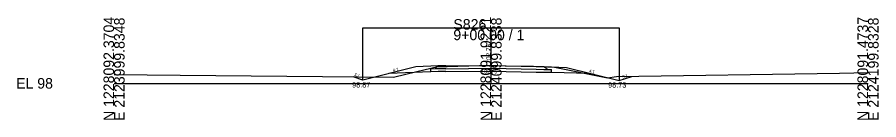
# Model space of a CAD drawing. Extents: x 2118382 to 2118616, y 1213030 to 1222057.
# Drawn here: x 2118381.9 to 2118610.4, y 1219530.1 to 1219557.4 of the extents above; entities that cross this region are included whole.
import ezdxf

# ---------------------------------------------------------------- set-up
doc = ezdxf.new("R2010")
doc.units = 0
for name, color, linetype in [('XS_CELL', 7, 'Continuous'), ('XS_M_DITCH', 7, 'Continuous'), ('XS_P_FINISHED_GRADE', 7, 'Continuous'), ('XS_P_FINISHED_GRADE_ELEV_TX', 7, 'Continuous'), ('XS_P_SUBGRADE_GRANULAR', 7, 'Continuous'), ('XS_P_SUBGRADE_PAVEMENT', 7, 'Continuous'), ('XS_P_TX_DCH', 7, 'Continuous'), ('XS_P_TX_FS_BS', 7, 'Continuous'), ('XS_X_GROUND', 7, 'Continuous'), ('XS_X_GROUND_TX', 7, 'Continuous')]:
    doc.layers.add(name, color=color, linetype=linetype)

msp = doc.modelspace()

# ---------------------------------------------------------------- linework, layer by layer
at = {"layer": 'XS_CELL'}
for p, q in [((2118507.6, 1219539.8), (2118507.6, 1219554.07)), ((2118407.6, 1219539.8), (2118507.6, 1219539.8)), ((2118507.6, 1219539.8), (2118607.6, 1219539.8))]:
    msp.add_line(p, q, dxfattribs=at)
at = {"layer": 'XS_M_DITCH'}
for p, q in [((2118473.6, 1219540.68), (2118473.6, 1219554.55)), ((2118473.6, 1219554.55), (2118541.6, 1219554.55)), ((2118541.6, 1219554.55), (2118541.6, 1219540.53))]:
    msp.add_line(p, q, dxfattribs=at)
at = {"layer": 'XS_P_FINISHED_GRADE'}
for p, q in [((2118487.6, 1219544.18), (2118473.6, 1219540.68)), ((2118493.6, 1219544.42), (2118487.6, 1219544.18)), ((2118495.6, 1219544.44), (2118493.6, 1219544.42)), ((2118495.6, 1219544.44), (2118507.6, 1219544.55)), ((2118507.6, 1219544.55), (2118519.6, 1219544.31)), ((2118519.6, 1219544.31), (2118521.6, 1219544.27)), ((2118521.6, 1219544.27), (2118527.6, 1219544.03)), ((2118527.6, 1219544.03), (2118541.6, 1219540.53)), ((2118473.6, 1219540.68), (2118471, 1219541.54)), ((2118541.6, 1219540.53), (2118544.93, 1219541.64))]:
    msp.add_line(p, q, dxfattribs=at)
at = {"layer": 'XS_P_SUBGRADE_GRANULAR'}
for p, q in [((2118492.73, 1219543.66), (2118491.6, 1219543.61)), ((2118491.6, 1219542.84), (2118480.46, 1219542.39)), ((2118491.6, 1219542.84), (2118491.6, 1219543.61)), ((2118493.6, 1219542.92), (2118491.6, 1219542.84)), ((2118495.6, 1219542.94), (2118493.6, 1219542.92)), ((2118495.6, 1219542.94), (2118507.6, 1219543.05)), ((2118507.6, 1219543.05), (2118519.6, 1219542.81)), ((2118519.6, 1219542.81), (2118521.6, 1219542.77)), ((2118521.6, 1219542.77), (2118523.6, 1219542.73)), ((2118522.46, 1219543.49), (2118523.6, 1219543.44)), ((2118523.6, 1219542.73), (2118523.6, 1219543.44)), ((2118523.6, 1219542.73), (2118533.6, 1219542.53))]:
    msp.add_line(p, q, dxfattribs=at)
at = {"layer": 'XS_P_SUBGRADE_PAVEMENT'}
for p, q in [((2118492.91, 1219543.96), (2118492.73, 1219543.66)), ((2118495.6, 1219543.69), (2118492.73, 1219543.66)), ((2118493.6, 1219544.42), (2118492.91, 1219543.96)), ((2118495.6, 1219543.69), (2118507.6, 1219543.8)), ((2118507.6, 1219543.8), (2118519.6, 1219543.56)), ((2118521.6, 1219544.27), (2118522.28, 1219543.8)), ((2118522.28, 1219543.8), (2118522.46, 1219543.49)), ((2118519.6, 1219543.56), (2118521.6, 1219543.52)), ((2118521.6, 1219543.52), (2118522.46, 1219543.49))]:
    msp.add_line(p, q, dxfattribs=at)
at = {"layer": 'XS_X_GROUND'}
for p, q in [((2118487.87, 1219542.98), (2118493.49, 1219544.31)), ((2118493.49, 1219544.31), (2118494.11, 1219544.31)), ((2118494.11, 1219544.31), (2118495.94, 1219544.3)), ((2118495.94, 1219544.3), (2118504.49, 1219544.5)), ((2118504.49, 1219544.5), (2118505.89, 1219544.53)), ((2118505.89, 1219544.53), (2118507.18, 1219544.56)), ((2118507.18, 1219544.56), (2118507.6, 1219544.55)), ((2118507.6, 1219544.55), (2118509.34, 1219544.52)), ((2118509.34, 1219544.52), (2118511.38, 1219544.48)), ((2118511.38, 1219544.48), (2118518.82, 1219544.34)), ((2118518.82, 1219544.34), (2118524.45, 1219544.09)), ((2118524.45, 1219544.09), (2118538.52, 1219541.28)), ((2118407.6, 1219542.11), (2118425.1, 1219541.98)), ((2118425.1, 1219541.98), (2118481.71, 1219541.44)), ((2118481.71, 1219541.44), (2118487.87, 1219542.98)), ((2118538.52, 1219541.28), (2118540.87, 1219541.58)), ((2118540.87, 1219541.58), (2118600.07, 1219542.55)), ((2118600.07, 1219542.55), (2118607.6, 1219542.7))]:
    msp.add_line(p, q, dxfattribs=at)

# ---------------------------------------------------------------- texts
at = {"layer": 'XS_CELL'}
for s, p in [('N 1228092.3704', (2118407.6, 1219529.8)), ('E 2123999.8348', (2118410.4, 1219529.8)), ('N 1228091.9221', (2118507.6, 1219529.8)), ('E 2124099.8338', (2118510.4, 1219529.8)), ('N 1228091.4737', (2118607.6, 1219529.8)), ('E 2124199.8328', (2118610.4, 1219529.8))]:
    msp.add_text(s, height=2.8, rotation=90, dxfattribs=at).set_placement(p)
for s, p in [('S826', (2118497.6, 1219554.07)), ('9+00.00 / 1', (2118497.6, 1219551.27)), ('EL 98', (2118381.6, 1219538.4))]:
    msp.add_text(s, height=2.8, dxfattribs=at).set_placement(p)
at = {"layer": 'XS_P_FINISHED_GRADE_ELEV_TX'}
msp.add_text(' 102.75', height=1.25, rotation=90, dxfattribs=at).set_placement((2118507.6, 1219544.55))
at = {"layer": 'XS_P_TX_DCH'}
for s, p in [('98.87', (2118470.74, 1219538.7)), ('98.73', (2118538.65, 1219538.67))]:
    msp.add_text(s, height=1.4, dxfattribs=at).set_placement(p)
at = {"layer": 'XS_P_TX_FS_BS'}
for s, rotation, p in [('4:1', 14.0362, (2118481.65, 1219542.84)), ('3:1', 341.5651, (2118471.21, 1219541.88)), ('4:1', 345.9638, (2118533.53, 1219542.76)), ('3:1', 18.4349, (2118542.5, 1219541.06))]:
    msp.add_text(s, height=0.8, rotation=rotation, dxfattribs=at).set_placement(p)
at = {"layer": 'XS_X_GROUND_TX'}
msp.add_text('102.75', height=1, dxfattribs=at).set_placement((2118505.03, 1219542.43))

doc.saveas('drawing.dxf')
